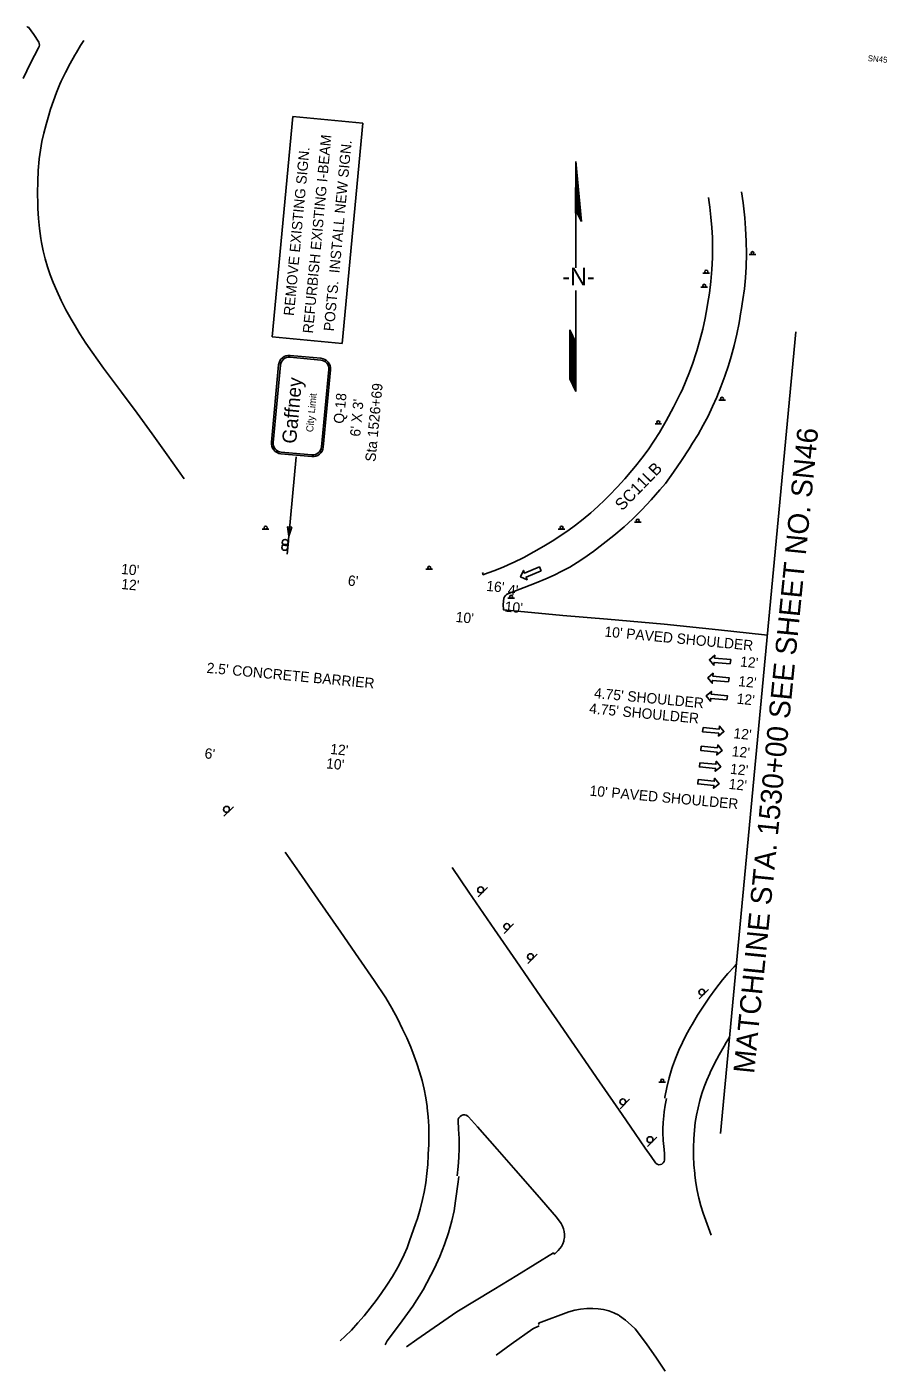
# Model space of a CAD drawing. Extents: x 1798880 to 1800499, y 1187704 to 1188705.
# Drawn here: x 1799916 to 1800499, y 1187727 to 1188639 of the extents above; entities that cross this region are included whole.
import ezdxf

# ---------------------------------------------------------------- set-up
doc = ezdxf.new("R2010")
doc.units = 0
for name, color, linetype in [('RD_EX_Road', 7, 'Continuous'), ('RD_PD_Final_LnLine', 7, 'Continuous'), ('RD_PD_Final_TX', 7, 'Continuous'), ('RD_SHT_MatchLine', 7, 'Continuous'), ('RD_SHT_TX', 7, 'Continuous'), ('RD_Sketch1', 7, 'Continuous'), ('RD_TX_RoadID', 7, 'Continuous'), ('SN_P_Signs', 7, 'Continuous')]:
    doc.layers.add(name, color=color, linetype=linetype)

# ---------------------------------------------------------------- blocks, each defined once
blk = doc.blocks.new('SARRW2')
at = {"layer": 'RD_PD_Final_LnLine'}
blk.add_lwpolyline([(-12, 1.2), (-12, -1.2), (-2.83, -1.2), (-2.83, -2.83), (0, 0), (-2.83, 2.83), (-2.83, 1.2)], close=True, dxfattribs=at)

msp = doc.modelspace()

# ---------------------------------------------------------------- linework, layer by layer
at = {"layer": 'RD_EX_Road'}
for points in [[(1799913.13, 1188603.71), (1799918.21, 1188614.11), (1799923.5, 1188624.4), (1799923.56, 1188624.48), (1799923.95, 1188625.36), (1799924.13, 1188626.3), (1799924.07, 1188627.26), (1799923.77, 1188628.18), (1799920.26, 1188633.46), (1799916.72, 1188638.37), (1799916.57, 1188638.48), (1799916.08, 1188638.63), (1799915.57, 1188638.55)], [(1800022.39, 1188332.27), (1800010.85, 1188348.51), (1800000.63, 1188362.79), (1799990.31, 1188376.78), (1799979.77, 1188391.04), (1799967.59, 1188407.33), (1799960.01, 1188418.02), (1799955.68, 1188424.22), (1799951.54, 1188430.56), (1799947.6, 1188437.02), (1799945.64, 1188440.42), (1799942.17, 1188446.71), (1799938.92, 1188453.12), (1799935.87, 1188459.63), (1799933.41, 1188465.35), (1799931.38, 1188470.6), (1799929.58, 1188475.94), (1799928, 1188481.35), (1799926.65, 1188486.82), (1799925.54, 1188492.34), (1799925.07, 1188495.09), (1799924.2, 1188501.85), (1799923.56, 1188508.63), (1799923.16, 1188515.42), (1799923.06, 1188518.47), (1799922.94, 1188526.09), (1799923.05, 1188533.72), (1799923.41, 1188541.34), (1799924, 1188548.94), (1799924.03, 1188549.24), (1799924.84, 1188555.08), (1799925.88, 1188560.89), (1799927.16, 1188566.65), (1799928.67, 1188572.36), (1799930.13, 1188577.14), (1799931.77, 1188582.87), (1799933.64, 1188588.57), (1799935.73, 1188594.19), (1799938.05, 1188599.71), (1799938.99, 1188601.79), (1799941.83, 1188607.81), (1799944.89, 1188613.74), (1799948.16, 1188619.55), (1799949.23, 1188621.35), (1799952.07, 1188626), (1799954.32, 1188629.35)], [(1800377.75, 1188522.92), (1800378.22, 1188519.52), (1800378.56, 1188516.46), (1800379.4, 1188509.61), (1800380, 1188502.71), (1800380.37, 1188495.8), (1800380.5, 1188488.87), (1800380.39, 1188481.97), (1800379.93, 1188474.02), (1800379.24, 1188466.08), (1800378.31, 1188458.18), (1800377.14, 1188450.31), (1800376.88, 1188448.75), (1800375.45, 1188441.23), (1800373.79, 1188433.76), (1800371.89, 1188426.33), (1800369.77, 1188418.98), (1800369.11, 1188416.87), (1800367.12, 1188410.64), (1800364.9, 1188404.47), (1800362.45, 1188398.39), (1800359.79, 1188392.4), (1800358.74, 1188390.19), (1800353.94, 1188380.76), (1800348.92, 1188371.44), (1800344.49, 1188363.6), (1800340.72, 1188357.69), (1800336.77, 1188351.93), (1800332.61, 1188346.31), (1800328.27, 1188340.84), (1800325.8, 1188337.89), (1800320.95, 1188332.17), (1800315.9, 1188326.59), (1800310.68, 1188321.18), (1800307.53, 1188318.07), (1800302.81, 1188313.49), (1800297.92, 1188309.07), (1800292.87, 1188304.83), (1800287.68, 1188300.78), (1800282.34, 1188296.92), (1800279.25, 1188294.82), (1800272.77, 1188290.55), (1800266.16, 1188286.49), (1800259.42, 1188282.62), (1800252.57, 1188278.97), (1800245.62, 1188275.53), (1800244.86, 1188275.17), (1800238.6, 1188272.38), (1800232.23, 1188269.81), (1800225.79, 1188267.46), (1800225.07, 1188267.21), (1800224.57, 1188268.69)], [(1800417.59, 1188226.31), (1800415.74, 1188226.51), (1800384.57, 1188229.9), (1800347.69, 1188233.58), (1800309.36, 1188237.04), (1800278.98, 1188239.56), (1800238.78, 1188243.31), (1800238.54, 1188247.05), (1800239.09, 1188251.33), (1800239.45, 1188252.26), (1800240.02, 1188253.07), (1800240.76, 1188253.73), (1800241.64, 1188254.19), (1800241.73, 1188254.23), (1800260.94, 1188261.73), (1800267.53, 1188264.36), (1800273.01, 1188266.83), (1800278.39, 1188269.52), (1800283.66, 1188272.42), (1800288.81, 1188275.52), (1800293.83, 1188278.82), (1800298.72, 1188282.32), (1800298.99, 1188282.52), (1800306.33, 1188288.05), (1800313.51, 1188293.78), (1800320.55, 1188299.69), (1800326.31, 1188304.76), (1800332.64, 1188311.24), (1800338.79, 1188317.88), (1800344.77, 1188324.67), (1800348.49, 1188329.09), (1800354.05, 1188336.76), (1800359.41, 1188344.57), (1800364.58, 1188352.52), (1800366.93, 1188356.29), (1800370.63, 1188362.33), (1800374.13, 1188368.5), (1800377.41, 1188374.78), (1800380.49, 1188381.17), (1800383.3, 1188387.55), (1800386.15, 1188394.63), (1800388.77, 1188401.81), (1800391.18, 1188409.06), (1800393.02, 1188415.19), (1800395.05, 1188422.7), (1800396.85, 1188430.25), (1800398.41, 1188437.87), (1800399.75, 1188445.52), (1800399.88, 1188446.36), (1800401.1, 1188453.73), (1800402.08, 1188461.13), (1800402.82, 1188468.56), (1800403.33, 1188476.01), (1800403.34, 1188476.05), (1800403.43, 1188484.66), (1800403.28, 1188493.26), (1800402.89, 1188501.86), (1800402.39, 1188509.05), (1800401.13, 1188519.38), (1800400.06, 1188526.68)], [(1800090.83, 1188078.97), (1800100.27, 1188065.49), (1800112.97, 1188047.18), (1800128.51, 1188024.9), (1800140.42, 1188007.52), (1800151.1, 1187992.14), (1800159, 1187980.28), (1800163.02, 1187973.3), (1800166.82, 1187966.23), (1800170.39, 1187959.11), (1800173.24, 1187953.09), (1800175.89, 1187946.96), (1800178.31, 1187940.75), (1800180.07, 1187935.75), (1800181.91, 1187930.06), (1800183.51, 1187924.29), (1800184.88, 1187918.46), (1800186.02, 1187912.58), (1800186.93, 1187906.67), (1800187.04, 1187905.78), (1800187.67, 1187899.55), (1800188.06, 1187893.29), (1800188.21, 1187887.02), (1800188.12, 1187880.75), (1800187.79, 1187874.5), (1800187.73, 1187873.63), (1800187.39, 1187867.38), (1800186.82, 1187861.11), (1800186, 1187854.86), (1800184.95, 1187848.65), (1800183.92, 1187843.6), (1800182.25, 1187837.1), (1800180.35, 1187830.69), (1800179.16, 1187827.05), (1800174.98, 1187815.5), (1800173.35, 1187810.91), (1800171.48, 1187806.37), (1800169.39, 1187801.93), (1800167.09, 1187797.62), (1800166.9, 1187797.29), (1800163.41, 1187791.33), (1800159.7, 1187785.49), (1800155.79, 1187779.78), (1800152.37, 1187775.1), (1800148.47, 1187769.88), (1800144.38, 1187764.79), (1800140.1, 1187759.85), (1800135.64, 1187755.07), (1800131.49, 1187750.92), (1800128, 1187747.82)], [(1800349.33, 1187911.97), (1800348.41, 1187907.51), (1800347.73, 1187903.01), (1800347.43, 1187900.35), (1800346.99, 1187895.88), (1800346.78, 1187891.39), (1800346.77, 1187888.99), (1800347.06, 1187883.55), (1800347.7, 1187877.51), (1800347.94, 1187874.57), (1800347.93, 1187871.6), (1800347.85, 1187870.29), (1800347.64, 1187869.3), (1800347.05, 1187868.33), (1800346.17, 1187867.61), (1800345.11, 1187867.21), (1800343.97, 1187867.19), (1800342.89, 1187867.54), (1800342.06, 1187868.17), (1800341.86, 1187868.39), (1800338.79, 1187872.82), (1800334.89, 1187878.47), (1800328.04, 1187888.39), (1800319.28, 1187901.17), (1800313.09, 1187909.94), (1800303.88, 1187923.27), (1800291.8, 1187940.74), (1800286.83, 1187947.88), (1800274.85, 1187965.38), (1800264.13, 1187981.04), (1800247.38, 1188005.37), (1800232.64, 1188026.75), (1800215.28, 1188052.03), (1800204.05, 1188068.67)], [(1800396.71, 1188003.14), (1800395.05, 1188001.43), (1800390.91, 1187996.85), (1800387.23, 1187992.45), (1800382.72, 1187986.69), (1800378.39, 1187980.79), (1800374.25, 1187974.75), (1800370.31, 1187968.58), (1800366.58, 1187962.29), (1800365.55, 1187960.47), (1800362.69, 1187955.33), (1800360.05, 1187950.08), (1800357.62, 1187944.72), (1800355.4, 1187939.28), (1800353.41, 1187933.74), (1800352.98, 1187932.45), (1800351.17, 1187926.05), (1800349.59, 1187919.58), (1800348.24, 1187913.06), (1800348.09, 1187912.23)], [(1800379.52, 1187819.34), (1800374.08, 1187834.32), (1800372.51, 1187839.36), (1800371.17, 1187844.47), (1800370.06, 1187849.63), (1800369.18, 1187854.84), (1800368.55, 1187860.07), (1800368.43, 1187861.31), (1800367.9, 1187867.13), (1800367.61, 1187872.99), (1800367.55, 1187878.85), (1800367.74, 1187884.71), (1800368.16, 1187890.55), (1800368.16, 1187890.61), (1800368.76, 1187895.71), (1800369.59, 1187900.78), (1800370.66, 1187905.81), (1800371.96, 1187910.78), (1800371.96, 1187910.8), (1800373.26, 1187915.45), (1800374.8, 1187920.06), (1800376.56, 1187924.59), (1800378.54, 1187929.02), (1800378.83, 1187929.63), (1800381.78, 1187935.72), (1800384.94, 1187941.72), (1800388.31, 1187947.61), (1800389.77, 1187950.01), (1800392.07, 1187953.54)], [(1800207.27, 1187859.66), (1800207.97, 1187865.91), (1800208.44, 1187872.16), (1800208.67, 1187878.43), (1800208.67, 1187878.53), (1800208.63, 1187884.89), (1800208.36, 1187891.24), (1800207.92, 1187896.88), (1800208.09, 1187897.98), (1800208.56, 1187899.01), (1800209.29, 1187899.88), (1800210.23, 1187900.51), (1800211.31, 1187900.87), (1800212.45, 1187900.92), (1800213.55, 1187900.66), (1800214.52, 1187900.12), (1800214.99, 1187899.71), (1800221.14, 1187892.82), (1800234.56, 1187877.59), (1800247.02, 1187863.19), (1800261.48, 1187846.7), (1800274.71, 1187831.57), (1800277.93, 1187827.36), (1800278.85, 1187825.59), (1800279.53, 1187823.74), (1800279.96, 1187821.82), (1800280.14, 1187819.86), (1800280.07, 1187817.89), (1800279.75, 1187815.97), (1800279.55, 1187815.22), (1800278.92, 1187813.46), (1800278.04, 1187811.78), (1800276.95, 1187810.24), (1800275.71, 1187808.91), (1800273.24, 1187806.61), (1800272.56, 1187807.34), (1800247.77, 1187792.03), (1800232.27, 1187782.64), (1800207.13, 1187767.35), (1800180.12, 1187748.61), (1800172.9, 1187743.62)], [(1800158.58, 1187744.96), (1800159.91, 1187747.75), (1800168.15, 1187758.81), (1800177.36, 1187771.17), (1800184.19, 1187782.34), (1800192.09, 1187797.12), (1800195.56, 1187804.96), (1800198.68, 1187812.96), (1800201.42, 1187821.08), (1800203.74, 1187829.16), (1800205.23, 1187835.91), (1800206.32, 1187842.68), (1800207.93, 1187855.6), (1800208.5, 1187859.19)], [(1800262.96, 1187758.72), (1800262.55, 1187759.65), (1800283.09, 1187767.33), (1800287.03, 1187768.52), (1800291.06, 1187769.33), (1800295.16, 1187769.74), (1800299.27, 1187769.77), (1800302.95, 1187769.45), (1800306.59, 1187768.92), (1800310.15, 1187768), (1800313.59, 1187766.71), (1800316.87, 1187765.05), (1800317.41, 1187764.74), (1800321.49, 1187761.76), (1800325.32, 1187758.48), (1800327.98, 1187755.87), (1800335.77, 1187745.63), (1800342.39, 1187736.04), (1800348.26, 1187727.22)], [(1800233.88, 1187737.92), (1800244.06, 1187745.4), (1800258.65, 1187755.8), (1800262.87, 1187757.87)]]:
    msp.add_lwpolyline(points, dxfattribs=at)
at = {"layer": 'RD_SHT_MatchLine'}
msp.add_line((1800436.83, 1188431.95), (1800385.96, 1187888.24), dxfattribs=at)
at = {"layer": 'RD_Sketch1'}
for p, q in [((1800287.81, 1188547.41), (1800287.6, 1188512.24)), ((1800291.53, 1188506.7), (1800287.81, 1188547.41)), ((1800287.81, 1188512.54), (1800287.81, 1188490.71)), ((1800288.11, 1188513.65), (1800291.53, 1188506.7)), ((1800287.81, 1188490.71), (1800287.81, 1188475.24)), ((1800287.81, 1188459.79), (1800287.81, 1188434.02)), ((1800283.82, 1188418.96), (1800283.82, 1188433.14)), ((1800283.82, 1188433.14), (1800287.81, 1188424.57)), ((1800287.81, 1188434.02), (1800287.81, 1188391.5)), ((1800283.82, 1188400.06), (1800283.82, 1188418.96)), ((1800287.81, 1188391.5), (1800283.82, 1188400.06))]:
    msp.add_line(p, q, dxfattribs=at)
for points in [[(1800287.82, 1188512.85), (1800287.82, 1188547.29)], [(1800287.92, 1188513.1), (1800287.92, 1188546.25)], [(1800288.01, 1188513.36), (1800288.01, 1188545.22)], [(1800288.1, 1188513.62), (1800288.1, 1188544.19)], [(1800288.2, 1188513.47), (1800288.2, 1188543.16)], [(1800288.29, 1188513.28), (1800288.29, 1188542.12)], [(1800288.39, 1188513.09), (1800288.39, 1188541.09)], [(1800288.48, 1188512.9), (1800288.48, 1188540.06)], [(1800288.58, 1188512.7), (1800288.58, 1188539.03)], [(1800288.67, 1188512.51), (1800288.67, 1188537.99)], [(1800287.73, 1188512.59), (1800287.73, 1188533.37)], [(1800288.77, 1188512.32), (1800288.77, 1188536.96)], [(1800288.86, 1188512.13), (1800288.86, 1188535.93)], [(1800288.96, 1188511.94), (1800288.96, 1188534.9)], [(1800289.05, 1188511.75), (1800289.05, 1188533.86)], [(1800289.14, 1188511.55), (1800289.14, 1188532.83)], [(1800289.24, 1188511.36), (1800289.24, 1188531.8)], [(1800289.33, 1188511.17), (1800289.33, 1188530.76)], [(1800289.43, 1188510.98), (1800289.43, 1188529.73)], [(1800289.52, 1188510.79), (1800289.52, 1188528.7)], [(1800289.62, 1188510.6), (1800289.62, 1188527.67)], [(1800289.71, 1188510.4), (1800289.71, 1188526.63)], [(1800289.81, 1188510.21), (1800289.81, 1188525.6)], [(1800289.9, 1188510.02), (1800289.9, 1188524.57)], [(1800289.99, 1188509.83), (1800289.99, 1188523.54)], [(1800290.09, 1188509.64), (1800290.09, 1188522.5)], [(1800290.18, 1188509.45), (1800290.18, 1188521.47)], [(1800290.28, 1188509.25), (1800290.28, 1188520.44)], [(1800287.63, 1188512.33), (1800287.63, 1188517.47)], [(1800290.37, 1188509.06), (1800290.37, 1188519.41)], [(1800290.47, 1188508.87), (1800290.47, 1188518.37)], [(1800290.56, 1188508.68), (1800290.56, 1188517.34)], [(1800290.66, 1188508.49), (1800290.66, 1188516.31)], [(1800290.75, 1188508.3), (1800290.75, 1188515.28)], [(1800290.84, 1188508.1), (1800290.84, 1188514.24)], [(1800290.94, 1188507.91), (1800290.94, 1188513.21)], [(1800291.03, 1188507.72), (1800291.03, 1188512.18)], [(1800291.13, 1188507.53), (1800291.13, 1188511.15)], [(1800291.22, 1188507.34), (1800291.22, 1188510.11)], [(1800291.32, 1188507.14), (1800291.32, 1188509.08)], [(1800291.41, 1188506.95), (1800291.41, 1188508.05)], [(1800291.51, 1188506.76), (1800291.51, 1188507.02)], [(1800283.89, 1188399.9), (1800283.89, 1188432.97)], [(1800283.99, 1188399.7), (1800283.99, 1188432.77)], [(1800284.08, 1188399.49), (1800284.08, 1188432.56)], [(1800284.18, 1188399.29), (1800284.18, 1188432.36)], [(1800284.27, 1188399.09), (1800284.27, 1188432.16)], [(1800284.37, 1188398.89), (1800284.37, 1188431.96)], [(1800284.46, 1188398.68), (1800284.46, 1188431.75)], [(1800284.56, 1188398.48), (1800284.56, 1188431.55)], [(1800284.65, 1188398.28), (1800284.65, 1188431.35)], [(1800284.74, 1188398.08), (1800284.74, 1188431.15)], [(1800284.84, 1188397.87), (1800284.84, 1188430.94)], [(1800284.93, 1188397.67), (1800284.93, 1188430.74)], [(1800285.03, 1188397.47), (1800285.03, 1188430.54)], [(1800285.12, 1188397.27), (1800285.12, 1188430.34)], [(1800285.22, 1188397.06), (1800285.22, 1188430.13)], [(1800285.31, 1188396.86), (1800285.31, 1188429.93)], [(1800285.41, 1188396.66), (1800285.41, 1188429.73)], [(1800285.5, 1188396.45), (1800285.5, 1188429.53)], [(1800285.59, 1188396.25), (1800285.59, 1188429.32)], [(1800285.69, 1188396.05), (1800285.69, 1188429.12)], [(1800285.78, 1188395.85), (1800285.78, 1188428.92)], [(1800285.88, 1188395.64), (1800285.88, 1188428.71)], [(1800285.97, 1188395.44), (1800285.97, 1188428.51)], [(1800286.07, 1188395.24), (1800286.07, 1188428.31)], [(1800286.16, 1188395.04), (1800286.16, 1188428.11)], [(1800286.26, 1188394.83), (1800286.26, 1188427.9)], [(1800286.35, 1188394.63), (1800286.35, 1188427.7)], [(1800286.45, 1188394.43), (1800286.45, 1188427.5)], [(1800286.54, 1188394.23), (1800286.54, 1188427.3)], [(1800286.63, 1188394.02), (1800286.63, 1188427.09)], [(1800286.73, 1188393.82), (1800286.73, 1188426.89)], [(1800286.82, 1188393.62), (1800286.82, 1188426.69)], [(1800286.92, 1188393.42), (1800286.92, 1188426.49)], [(1800287.01, 1188393.21), (1800287.01, 1188426.28)], [(1800287.11, 1188393.01), (1800287.11, 1188426.08)], [(1800287.2, 1188392.81), (1800287.2, 1188425.88)], [(1800287.3, 1188392.6), (1800287.3, 1188425.68)], [(1800287.39, 1188392.4), (1800287.39, 1188425.47)], [(1800287.48, 1188392.2), (1800287.48, 1188425.27)], [(1800287.58, 1188392), (1800287.58, 1188425.07)], [(1800287.67, 1188391.79), (1800287.67, 1188424.86)], [(1800287.77, 1188391.59), (1800287.77, 1188424.66)]]:
    msp.add_lwpolyline(points, dxfattribs=at)
at = {"layer": 'SN_P_Signs'}
for p, q in [((1800081.91, 1188428.42), (1800095.88, 1188577.79)), ((1800095.88, 1188577.79), (1800143.29, 1188573.35)), ((1800143.29, 1188573.35), (1800129.32, 1188423.98)), ((1800405.29, 1188484.23), (1800409.79, 1188484.23)), ((1800373.99, 1188471.64), (1800378.49, 1188471.64)), ((1800372.61, 1188462.12), (1800377.11, 1188462.12)), ((1800129.32, 1188423.98), (1800081.91, 1188428.42)), ((1800081.41, 1188357.03), (1800086.31, 1188409.4)), ((1800384.66, 1188385.51), (1800389.16, 1188385.51)), ((1800341.47, 1188369.53), (1800345.97, 1188369.53)), ((1800093.19, 1188293.36), (1800098.21, 1188347.02)), ((1800327.51, 1188302.89), (1800332.01, 1188302.89)), ((1800075.25, 1188298.06), (1800079.75, 1188298.06)), ((1800092.3, 1188284.41), (1800093.19, 1188293.36)), ((1800275.89, 1188298.11), (1800280.39, 1188298.11)), ((1800092.03, 1188281.04), (1800092.92, 1188290)), ((1800186.17, 1188270.91), (1800190.67, 1188270.91)), ((1800241.66, 1188251.23), (1800246.16, 1188251.23)), ((1800049.28, 1188103.49), (1800055.65, 1188109.85)), ((1800221.53, 1188048.83), (1800227.9, 1188055.2)), ((1800239.28, 1188024.03), (1800245.64, 1188030.39)), ((1800255.27, 1188003.56), (1800261.64, 1188009.93)), ((1800371.4, 1187979.54), (1800377.77, 1187985.9)), ((1800344.09, 1187923.17), (1800348.59, 1187923.17)), ((1800317.92, 1187905.16), (1800324.28, 1187911.53)), ((1800336.32, 1187879.55), (1800342.68, 1187885.91))]:
    msp.add_line(p, q, dxfattribs=at)
for points in [[(1800094.04, 1188414.7), (1800114.86, 1188412.76)], [(1800094.15, 1188415.9), (1800114.97, 1188413.95)], [(1800082.61, 1188356.92), (1800087.5, 1188409.29)], [(1800120.28, 1188406.22), (1800115.38, 1188353.85)], [(1800121.47, 1188406.11), (1800116.57, 1188353.74)], [(1800108.73, 1188347.24), (1800087.91, 1188349.19)], [(1800108.84, 1188348.44), (1800088.02, 1188350.38)]]:
    msp.add_lwpolyline(points, dxfattribs=at)
msp.add_lwpolyline([(1800095.29, 1188299.35), (1800093.19, 1188293.36), (1800092.23, 1188299.63)], close=True, dxfattribs=at)
for centre, radius in [((1800407.55, 1188485.24), 1), ((1800376.25, 1188472.66), 1), ((1800374.87, 1188463.13), 1), ((1800386.91, 1188386.52), 1), ((1800343.72, 1188370.55), 1), ((1800329.76, 1188303.9), 1), ((1800077.51, 1188299.08), 1), ((1800278.15, 1188299.12), 1), ((1800090.46, 1188285.73), 2), ((1800090.73, 1188289.1), 2), ((1800188.42, 1188271.92), 1), ((1800243.92, 1188252.24), 1), ((1800051.04, 1188108.11), 2), ((1800223.3, 1188053.46), 2), ((1800241.04, 1188028.65), 2), ((1800257.04, 1188008.19), 2), ((1800373.17, 1187984.16), 2), ((1800346.35, 1187924.18), 1), ((1800319.68, 1187909.79), 2), ((1800338.08, 1187884.17), 2)]:
    msp.add_circle(centre, radius, dxfattribs=at)
for centre, radius, start, end in [((1800093.48, 1188408.73), 7.2, 84.65568, 174.65568), ((1800093.48, 1188408.73), 6, 84.65568, 174.65568), ((1800114.3, 1188406.78), 6, 354.65568, 84.65568), ((1800114.3, 1188406.78), 7.2, 354.65568, 84.65568), ((1800088.58, 1188356.36), 7.2, 174.65568, 264.65568), ((1800088.58, 1188356.36), 6, 174.65568, 264.65568), ((1800109.4, 1188354.41), 7.2, 264.65568, 354.65568), ((1800109.4, 1188354.41), 6, 264.65568, 354.65568)]:
    msp.add_arc(centre, radius, start, end, dxfattribs=at)

# ---------------------------------------------------------------- block references
at = {"layer": 'RD_PD_Final_LnLine'}
for p, xscale, yscale, rotation in [((1800250.35, 1188265.68), 1.1999999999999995, 1.200000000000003, -157.74119373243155), ((1800378.32, 1188209.51), 1.1999999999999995, 1.200000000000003, 174.65567699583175), ((1800377.18, 1188197.27), 1.1999999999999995, 1.200000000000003, 174.65567699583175), ((1800376.04, 1188185.04), 1.1999999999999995, 1.200000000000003, 174.65567699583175), ((1800388.23, 1188160.81), 1.1999999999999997, 1.2000000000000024, -5.34432300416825), ((1800387.04, 1188148.09), 1.1999999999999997, 1.2000000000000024, -5.34432300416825), ((1800386, 1188136.97), 1.1999999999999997, 1.2000000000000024, -5.34432300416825), ((1800384.92, 1188125.46), 1.1999999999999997, 1.2000000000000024, -5.34432300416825)]:
    msp.add_blockref('SARRW2', p, dxfattribs=dict(at, xscale=xscale, yscale=yscale, rotation=rotation))

# ---------------------------------------------------------------- texts
at = {"layer": 'RD_PD_Final_TX'}
for s, rotation, p in [("10'", 354.65568, (1799979.3, 1188267.73)), ("6'", 354.65568, (1800133.02, 1188259.9)), ("12'", 354.65568, (1799979.39, 1188257.52)), ("16'", 354.65568, (1800226.87, 1188256.25)), ("4'", 354.65568, (1800241.48, 1188253.58)), ("10'", 354.65568, (1800239.35, 1188242.19)), ("10'", 354.65568, (1800206.11, 1188235.19)), ("10' PAVED SHOULDER", 354.54177, (1800306.97, 1188225.29)), ("12'", 354.27886, (1800398.93, 1188204.99)), ("2.5' CONCRETE BARRIER", 354.65741, (1800037.31, 1188200.68)), ("12'", 353.95121, (1800397.68, 1188191.7)), ("4.75' SHOULDER", 354.65568, (1800299.95, 1188183.58)), ("12'", 354.52886, (1800396.58, 1188179.78)), ("4.75' SHOULDER", 354.65568, (1800296.65, 1188173.2)), ("12'", 354.20121, (1800394.39, 1188156.37)), ("6'", 354.65568, (1800035.92, 1188142.69)), ("12'", 354.65568, (1800121.07, 1188145.68)), ("12'", 354.20121, (1800393.24, 1188144.16)), ("10'", 354.65568, (1800118.28, 1188135.9)), ("12'", 353.95121, (1800392.13, 1188132.27)), ("12'", 353.95121, (1800391.17, 1188122.01)), ("10' PAVED SHOULDER", 354.79177, (1800296.89, 1188117.4))]:
    msp.add_text(s, height=7, rotation=rotation, dxfattribs=at).set_placement(p)
at = {"layer": 'RD_SHT_TX'}
for s, height, rotation, p in [('SN45', 4, 354.65567, (1800485.54, 1188615.47)), ('MATCHLINE STA. 1530+00 SEE SHEET NO. SN46', 14.1726, 84.31294, (1800408.65, 1187928.52))]:
    msp.add_text(s, height=height, rotation=rotation, dxfattribs=at).set_placement(p)
at = {"layer": 'RD_Sketch1'}
msp.add_text('-N-', height=11.811, rotation=0, dxfattribs=at).set_placement((1800278.61, 1188463.5))
at = {"layer": 'RD_TX_RoadID'}
msp.add_text('SC11LB', height=8, rotation=45.79807, dxfattribs=at).set_placement((1800319.19, 1188310.09))
at = {"layer": 'SN_P_Signs'}
for s, height, rotation, p in [('REFURBISH EXISTING I-BEAM', 6.9998, 84.65576, (1800109.59, 1188430.58)), ('REMOVE EXISTING SIGN.', 6.9998, 84.65576, (1800096.65, 1188442.49)), ('POSTS.  INSTALL NEW SIGN.', 6.9998, 84.65576, (1800123.79, 1188432.04)), ('Gaffney', 9.6, 84.65568, (1800098.11, 1188355.73)), ('Sta 1526+69', 7, 84.65576, (1800151.95, 1188343.57)), ('City Limit', 4.8, 84.65568, (1800109.67, 1188363.7)), ('Q-18', 7, 84.65576, (1800130.46, 1188369.33)), ("6' X 3'", 7, 84.65576, (1800141.59, 1188360.6))]:
    msp.add_text(s, height=height, rotation=rotation, dxfattribs=at).set_placement(p)

doc.saveas('drawing.dxf')
